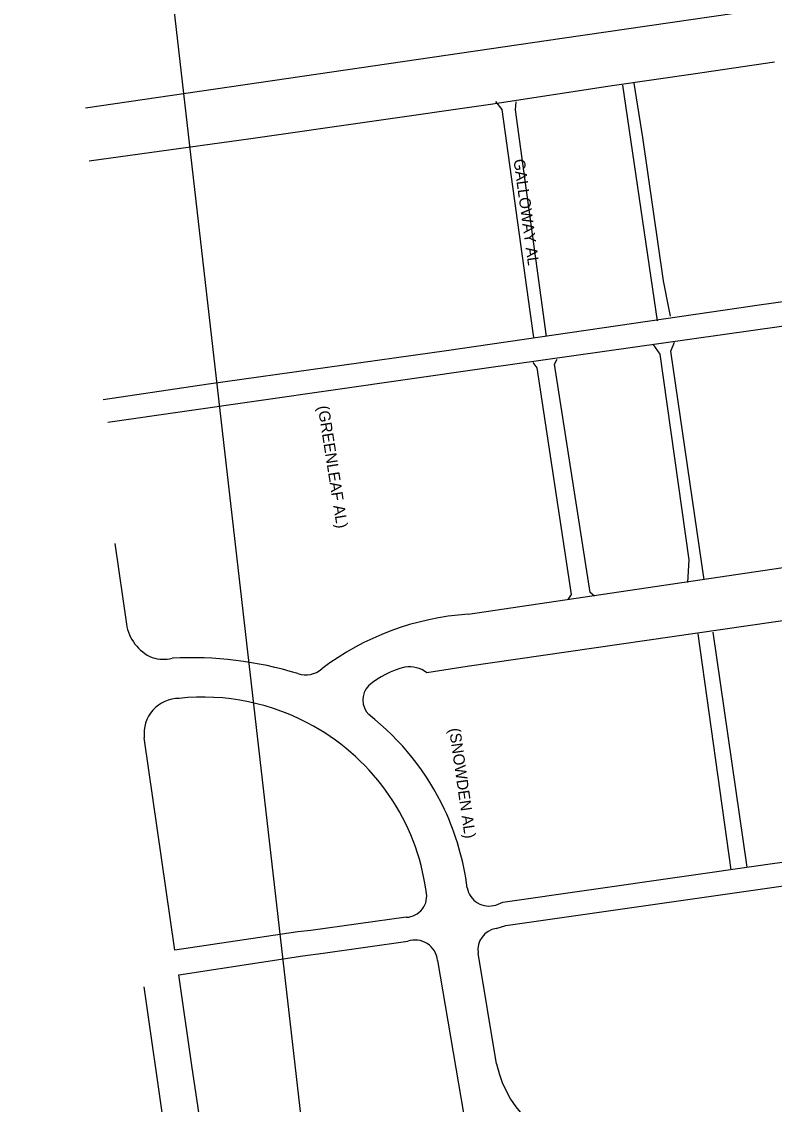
# Model space of a CAD drawing. Extents: x -9648 to 41057, y -12373 to 40276.
# Drawn here: x 8174 to 8842, y -3428 to -2467 of the extents above; entities that cross this region are included whole.
import ezdxf

# ---------------------------------------------------------------- set-up
doc = ezdxf.new("R2010")
doc.units = 0
doc.layers.add('SC_Scratch1', color=7, linetype='Continuous')
doc.layers.add('SH_Data', color=7, linetype='Continuous')

msp = doc.modelspace()

# ---------------------------------------------------------------- linework, layer by layer
at = {"layer": 'SC_Scratch1'}
msp.add_line((8431.69, -3520.73), (8174.5, -1275.41), dxfattribs=at)
at = {"layer": 'SH_Data'}
for p, q in [((8707.36, -2523.56), (8738.08, -2732.74)), ((8234.34, -2590.71), (8377.59, -2570.94)), ((8570.37, -2993), (9014.19, -2926.99)), ((8257.09, -2930.36), (8267.38, -3001.66)), ((8941.82, -2985.62), (8569.59, -3039.21)), ((8774.04, -3010.32), (8803.35, -3219.7)), ((8817.95, -3217.49), (8787.63, -3008.91)), ((8569.59, -3039.21), (8533.77, -3044.85)), ((8441.96, -3293.75), (8516.8, -3283.15)), ((8595.7, -3391.96), (8579.24, -3293.54)), ((8543.37, -3300.12), (8569.89, -3456.99)), ((8282.69, -3323.49), (8308.9, -3506.38))]:
    msp.add_line(p, q, dxfattribs=at)
for points in [[(8902.32, -2445.85), (8653.74, -2482.19), (8231.2, -2543.89)], [(8377.59, -2570.94), (8590.17, -2540.42), (8698.16, -2523.76), (8770.09, -2513.5), (8841.95, -2502.88)], [(8717.36, -2521.95), (8724.99, -2569.95), (8743.46, -2697.34), (8748.07, -2721.23), (8749.48, -2728.53)], [(8594.57, -2538.22), (8600.18, -2545.22), (8625.27, -2724.3), (8628.49, -2747.6)], [(8612.57, -2538.41), (8611.98, -2545.61), (8639.69, -2746.59)], [(9089.85, -2680.34), (8959.26, -2700.42), (8826.37, -2719.09), (8812.67, -2721.1), (8551.29, -2759.24), (8340.11, -2788.96), (8246.72, -2802.82)], [(9076.86, -2703.75), (9008.37, -2714.49), (8980.07, -2719), (8584.5, -2775.03), (8250.93, -2822.81)], [(8734.09, -2753.34), (8740.29, -2762.14), (8766, -2944.72), (8765.01, -2964.72)], [(8779.81, -2962.52), (8750.29, -2759.73), (8753.49, -2751.53)], [(8659.02, -2979.78), (8662.02, -2975.58), (8631.5, -2774.4), (8628.1, -2769.6)], [(8682.62, -2976.97), (8678.62, -2973.77), (8646.9, -2770.99), (8649.3, -2766.59)], [(8515.61, -3261.85), (8430.91, -3273.62), (8419.35, -3274.86), (8310.39, -3290.98), (8283.26, -3102.5)], [(8594.92, -3250.96), (8601.1, -3248.39), (8834.15, -3215.09), (8941.34, -3200.03)], [(8595.19, -3271.7), (8603.83, -3269), (8891.36, -3228.05), (8950.75, -3221.02)], [(8342.31, -3506.16), (8325.45, -3393.37), (8313.81, -3312.78), (8423.81, -3296.02), (8441.96, -3293.75)]]:
    msp.add_lwpolyline(points, dxfattribs=at)
for centre, radius, start, end in [((8586.37, -3234.2), 241.72, 93.79518, 127.07818), ((8305.58, -2995.92), 38.63, 188.54718, 246.77618), ((8300.05, -3002.4), 30.6, 251.50618, 284.90818), ((8324.93, -3355.24), 323.71, 73.01218, 93.01018), ((8426.37, -3025.32), 21.46, 251.35018, 311.66718), ((8534.71, -3120.2), 82.75, 104.24518, 129.62518), ((8518.46, -3064.85), 25.19, 52.56918, 99.39418), ((8495.27, -3069.01), 18.31, 136.73918, 225.25518), ((8314.16, -3098.79), 31.12, 90.15118, 186.83518), ((8335.41, -3264.97), 198.45, 60.45618, 96.17018), ((8336.91, -3267.12), 235.43, 25.39418, 51.83618), ((8336.33, -3265.79), 198.71, 7.83618, 60.80318), ((8326.02, -3268.2), 245.76, 7.59818, 24.53318), ((8588.94, -3232.28), 19.62, 190.05618, 287.76218), ((8514.89, -3243.06), 18.81, 272.19518, 13.41018), ((8598.48, -3290.85), 19.43, 99.75118, 187.97218), ((8523.37, -3302.16), 20.11, 5.82018, 109.06118), ((8689.45, -3372.87), 95.67, 191.51018, 271.29718)]:
    msp.add_arc(centre, radius, start, end, dxfattribs=at)

# ---------------------------------------------------------------- texts
at = {"layer": 'SC_Scratch1'}
for s, rotation, p in [('GALLOWAY AL', 277.87218, (8610.61, -2589.83)), ('(GREENLEAF AL)', 278.92718, (8436.97, -2808.69)), ('(SNOWDEN AL)', 278.18018, (8553.45, -3094.65))]:
    msp.add_text(s, height=10, rotation=rotation, dxfattribs=at).set_placement(p)

doc.saveas('drawing.dxf')
